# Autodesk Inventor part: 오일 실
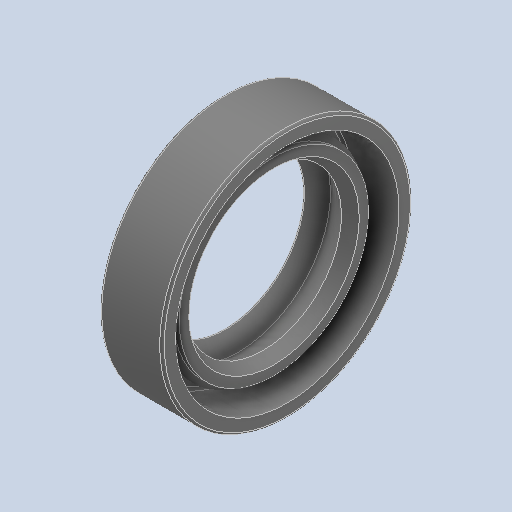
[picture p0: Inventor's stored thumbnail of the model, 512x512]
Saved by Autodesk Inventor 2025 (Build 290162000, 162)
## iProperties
Created: 2024-08
Part Number: 오일 실
Material: 고무
Description: 오일-실
Document SubType Name: Modeling
Designer: SAMSUNG
Density: 0.93 g/cm^3
Appearance: 기본값
Author: jhkim
Sending System: Autodesk Inventor 2025
Preprocessor: ST-DEVELOPER v20
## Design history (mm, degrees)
feature "Solid1"
node "솔리드1"
